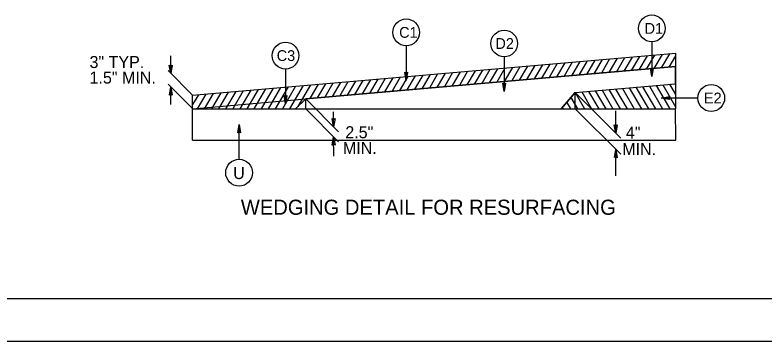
# Model space of a CAD drawing. Extents: x 1553884 to 1554215, y 810431 to 810779.
# Drawn here: x 1554013.4 to 1554073.1, y 810614.4 to 810640.4 of the extents above; entities that cross this region are included whole.
import ezdxf

# ---------------------------------------------------------------- set-up
doc = ezdxf.new("R2010")
doc.units = 0
for name, color, linetype in [('Old_Level_2', 7, 'Continuous'), ('Old_Level_20', 7, 'Continuous'), ('Prop CMT Steel Beam Girder', 7, 'Continuous'), ('Prop Lane Arrow CELL', 7, 'Continuous'), ('Prop Terminator CELL', 7, 'Continuous'), ('Typical Detail Pavement Repair CELL', 7, 'Continuous')]:
    doc.layers.add(name, color=color, linetype=linetype)

msp = doc.modelspace()

# ---------------------------------------------------------------- linework, layer by layer
at = {"layer": 'Old_Level_2'}
msp.add_line((1553906.821, 810617.805), (1554154.321, 810617.805), dxfattribs=at)
at = {"layer": 'Old_Level_20'}
for p, q in [((1554064.146, 810638.233), (1554064.146, 810635.474)), ((1554044.579, 810637.915), (1554044.579, 810635.156)), ((1554025.828, 810635.725), (1554025.826, 810637.124)), ((1554027.566, 810633.987), (1554066.022, 810637.323)), ((1554052.384, 810637.033), (1554052.384, 810634.273)), ((1554060.19, 810636.817), (1554059.535, 810635.696)), ((1554060.786, 810636.869), (1554060.131, 810635.747)), ((1554061.382, 810636.921), (1554060.727, 810635.799)), ((1554061.977, 810636.972), (1554061.322, 810635.85)), ((1554062.573, 810637.024), (1554061.918, 810635.902)), ((1554063.169, 810637.076), (1554062.513, 810635.954)), ((1554063.764, 810637.127), (1554063.109, 810636.006)), ((1554064.36, 810637.179), (1554063.705, 810636.057)), ((1554064.956, 810637.231), (1554064.3, 810636.109)), ((1554065.551, 810637.282), (1554064.896, 810636.161)), ((1554066.023, 810637.122), (1554065.492, 810636.212)), ((1554066.022, 810637.323), (1554066.027, 810636.259)), ((1554036.574, 810633.704), (1554066.027, 810636.259)), ((1554053.042, 810636.197), (1554052.387, 810635.076)), ((1554053.638, 810636.249), (1554052.983, 810635.127)), ((1554054.234, 810636.3), (1554053.579, 810635.179)), ((1554054.829, 810636.352), (1554054.174, 810635.231)), ((1554055.425, 810636.404), (1554054.77, 810635.282)), ((1554056.021, 810636.456), (1554055.365, 810635.334)), ((1554056.616, 810636.507), (1554055.961, 810635.386)), ((1554057.212, 810636.559), (1554056.557, 810635.437)), ((1554057.808, 810636.611), (1554057.153, 810635.489)), ((1554058.404, 810636.662), (1554057.748, 810635.541)), ((1554058.999, 810636.714), (1554058.344, 810635.592)), ((1554059.595, 810636.766), (1554058.939, 810635.644)), ((1554066.027, 810636.259), (1554066.043, 810632.904)), ((1554025.607, 810635.947), (1554027.566, 810633.987)), ((1554034.967, 810636.07), (1554034.967, 810633.311)), ((1554045.894, 810635.577), (1554045.239, 810634.456)), ((1554046.49, 810635.629), (1554045.835, 810634.507)), ((1554047.086, 810635.68), (1554046.431, 810634.559)), ((1554047.681, 810635.732), (1554047.026, 810634.611)), ((1554048.277, 810635.784), (1554047.622, 810634.662)), ((1554048.873, 810635.835), (1554048.217, 810634.714)), ((1554049.468, 810635.887), (1554048.813, 810634.766)), ((1554050.064, 810635.939), (1554049.409, 810634.817)), ((1554050.66, 810635.99), (1554050.005, 810634.869)), ((1554051.255, 810636.042), (1554050.6, 810634.921)), ((1554051.851, 810636.094), (1554051.196, 810634.972)), ((1554052.447, 810636.145), (1554051.791, 810635.024)), ((1554039.342, 810635.008), (1554038.687, 810633.887)), ((1554039.937, 810635.06), (1554039.283, 810633.939)), ((1554040.533, 810635.112), (1554039.878, 810633.991)), ((1554041.129, 810635.163), (1554040.474, 810634.042)), ((1554041.725, 810635.215), (1554041.07, 810634.094)), ((1554042.32, 810635.267), (1554041.665, 810634.146)), ((1554042.916, 810635.319), (1554042.261, 810634.197)), ((1554043.511, 810635.37), (1554042.857, 810634.249)), ((1554044.107, 810635.422), (1554043.452, 810634.301)), ((1554044.703, 810635.474), (1554044.048, 810634.352)), ((1554045.298, 810635.525), (1554044.643, 810634.404)), ((1554025.613, 810634.862), (1554027.572, 810632.902)), ((1554025.832, 810633.246), (1554025.83, 810634.645)), ((1554032.194, 810634.388), (1554031.325, 810632.902)), ((1554032.789, 810634.44), (1554031.89, 810632.902)), ((1554033.385, 810634.492), (1554032.456, 810632.902)), ((1554033.98, 810634.543), (1554033.021, 810632.902)), ((1554034.576, 810634.595), (1554033.587, 810632.902)), ((1554035.172, 810634.647), (1554034.153, 810632.902)), ((1554035.768, 810634.698), (1554034.718, 810632.902)), ((1554036.363, 810634.75), (1554035.284, 810632.902)), ((1554036.959, 810634.802), (1554035.958, 810633.088)), ((1554037.555, 810634.853), (1554036.9, 810633.732)), ((1554038.15, 810634.905), (1554037.496, 810633.784)), ((1554038.746, 810634.957), (1554038.091, 810633.836)), ((1554058.044, 810634.201), (1554066.034, 810634.893)), ((1554060.183, 810634.386), (1554061.05, 810632.903)), ((1554060.722, 810634.433), (1554061.615, 810632.903)), ((1554061.26, 810634.479), (1554062.18, 810632.903)), ((1554061.798, 810634.526), (1554062.746, 810632.903)), ((1554062.336, 810634.573), (1554063.311, 810632.903)), ((1554062.875, 810634.62), (1554063.877, 810632.903)), ((1554063.413, 810634.666), (1554064.442, 810632.904)), ((1554063.951, 810634.713), (1554065.008, 810632.904)), ((1554064.489, 810634.759), (1554065.573, 810632.904)), ((1554065.027, 810634.806), (1554066.042, 810633.069)), ((1554065.566, 810634.853), (1554066.038, 810634.045)), ((1554028.024, 810634.027), (1554027.566, 810633.243)), ((1554027.566, 810632.923), (1554027.566, 810633.987)), ((1554028.62, 810634.078), (1554027.932, 810632.901)), ((1554029.215, 810634.13), (1554028.498, 810632.901)), ((1554029.811, 810634.182), (1554029.063, 810632.901)), ((1554030.406, 810634.233), (1554029.628, 810632.902)), ((1554031.002, 810634.285), (1554030.194, 810632.902)), ((1554031.598, 810634.337), (1554030.76, 810632.902)), ((1554058.044, 810634.201), (1554056.935, 810632.903)), ((1554057.7, 810633.798), (1554058.222, 810632.903)), ((1554058.036, 810634.191), (1554058.788, 810632.903)), ((1554058.044, 810634.201), (1554061.668, 810630.577)), ((1554058.047, 810632.903), (1554058.044, 810634.201)), ((1554058.569, 810634.246), (1554059.353, 810632.903)), ((1554059.107, 810634.293), (1554059.918, 810632.903)), ((1554059.645, 810634.34), (1554060.484, 810632.903)), ((1554027.566, 810632.901), (1554036.574, 810633.704)), ((1554035.771, 810632.902), (1554036.574, 810633.704)), ((1554036.574, 810633.704), (1554039.196, 810631.085)), ((1554036.576, 810632.902), (1554036.574, 810633.704)), ((1554057.364, 810633.405), (1554057.657, 810632.903)), ((1554067.808, 810633.763), (1554064.895, 810633.763)), ((1554027.566, 810632.901), (1554066.043, 810632.904)), ((1554027.566, 810630.409), (1554027.566, 810632.901)), ((1554036.576, 810632.902), (1554039.196, 810630.279)), ((1554038.801, 810631.479), (1554038.8, 810632.663)), ((1554057.028, 810633.012), (1554057.092, 810632.903)), ((1554058.047, 810632.903), (1554061.668, 810629.284)), ((1554061.275, 810630.971), (1554061.276, 810632.732)), ((1554066.057, 810630.412), (1554066.043, 810632.904)), ((1554031.272, 810628.886), (1554031.272, 810631.646)), ((1554027.566, 810630.409), (1554066.057, 810630.412)), ((1554038.805, 810629.14), (1554038.802, 810630.673)), ((1554061.272, 810627.567), (1554061.274, 810629.678))]:
    msp.add_line(p, q, dxfattribs=at)
for centre in [(1554064.146, 810639.301), (1554044.579, 810638.983), (1554052.385, 810638.101), (1554034.967, 810637.138), (1554068.876, 810633.763), (1554031.272, 810627.819)]:
    msp.add_circle(centre, 1.068, dxfattribs=at)
at = {"layer": 'Prop CMT Steel Beam Girder'}
for points in [[(1554025.941, 810636.385), (1554025.828, 810635.725), (1554025.71, 810636.388), (1554025.827, 810636.304)], [(1554044.693, 810635.815), (1554044.579, 810635.156), (1554044.462, 810635.819), (1554044.579, 810635.734)], [(1554064.259, 810636.133), (1554064.146, 810635.474), (1554064.029, 810636.137), (1554064.146, 810636.052)], [(1554025.718, 810633.985), (1554025.83, 810634.645), (1554025.948, 810633.982), (1554025.831, 810634.066)], [(1554052.498, 810634.933), (1554052.384, 810634.273), (1554052.267, 810634.936), (1554052.384, 810634.852)], [(1554035.081, 810633.97), (1554034.967, 810633.311), (1554034.85, 810633.974), (1554034.967, 810633.889)], [(1554065.554, 810633.649), (1554064.895, 810633.763), (1554065.558, 810633.88), (1554065.473, 810633.763)], [(1554038.914, 810632.138), (1554038.801, 810631.479), (1554038.683, 810632.142), (1554038.8, 810632.057)], [(1554031.158, 810630.987), (1554031.272, 810631.646), (1554031.389, 810630.983), (1554031.272, 810631.067)], [(1554061.389, 810631.63), (1554061.275, 810630.971), (1554061.158, 810631.634), (1554061.275, 810631.549)], [(1554038.69, 810630.013), (1554038.802, 810630.673), (1554038.921, 810630.01), (1554038.803, 810630.094)], [(1554061.16, 810629.019), (1554061.274, 810629.678), (1554061.39, 810629.015), (1554061.273, 810629.1)]]:
    msp.add_lwpolyline(points, close=True, dxfattribs=at)
at = {"layer": 'Prop Lane Arrow CELL'}
msp.add_line((1553901.353, 810614.43), (1554156.35, 810614.43), dxfattribs=at)
at = {"layer": 'Prop Terminator CELL'}
msp.add_lwpolyline([(1554066.027, 810636.259), (1554036.574, 810633.704), (1554035.771, 810632.902), (1554056.935, 810632.903), (1554058.044, 810634.201), (1554066.034, 810634.893)], close=True, dxfattribs=at)

# ---------------------------------------------------------------- texts
at = {"layer": 'Old_Level_20'}
for s, height, p in [('3" TYP.', 0.9558, (1554019.356, 810636.149)), ('1.5" MIN.', 0.9558, (1554019.356, 810634.912)), ('2.5"', 0.9558, (1554039.73, 810630.563)), ('4"', 0.9558, (1554062.08, 810630.536)), ('MIN.', 0.9558, (1554039.537, 810629.311)), ('MIN.', 0.9558, (1554061.792, 810629.217)), ('WEDGING DETAIL FOR RESURFACING', 1.2, (1554031.408, 810624.473))]:
    msp.add_text(s, height=height, dxfattribs=at).set_placement(p)
at = {"layer": 'Typical Detail Pavement Repair CELL'}
for s, height, p in [('C1', 0.8608, (1554044.018, 810638.553)), ('D1', 0.8608, (1554063.572, 810638.871)), ('D2', 0.8608, (1554051.686, 810637.67)), ('C3', 0.8608, (1554034.267, 810636.708)), ('E2', 0.8608, (1554068.295, 810633.332)), ('U', 0.956, (1554030.798, 810627.314))]:
    msp.add_text(s, height=height, dxfattribs=at).set_placement(p)

doc.saveas('drawing.dxf')
